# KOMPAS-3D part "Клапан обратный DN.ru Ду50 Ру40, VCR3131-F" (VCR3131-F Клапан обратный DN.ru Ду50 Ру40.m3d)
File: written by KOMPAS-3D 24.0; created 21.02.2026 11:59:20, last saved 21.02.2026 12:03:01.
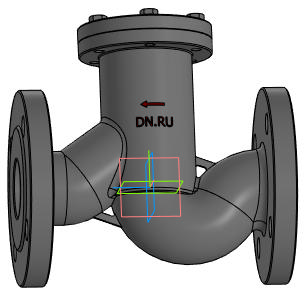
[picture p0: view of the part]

Document properties: Автор: R2D2; Полное имя файла: VCR3131-F Клапан обратный DN.ru Ду50 Ру40.cdw

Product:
- Part/product: Клапан обратный DN.ru Ду50 Ру40  | designation VCR3131-F
    Масса: 12
    Раздел спецификации: Прочие изделия
    Форматы листов документа: A2
    Примечание: D100-04041
    additional columns: D100-04041

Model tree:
1. Операция без истории:1

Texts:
  VCR3131-F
